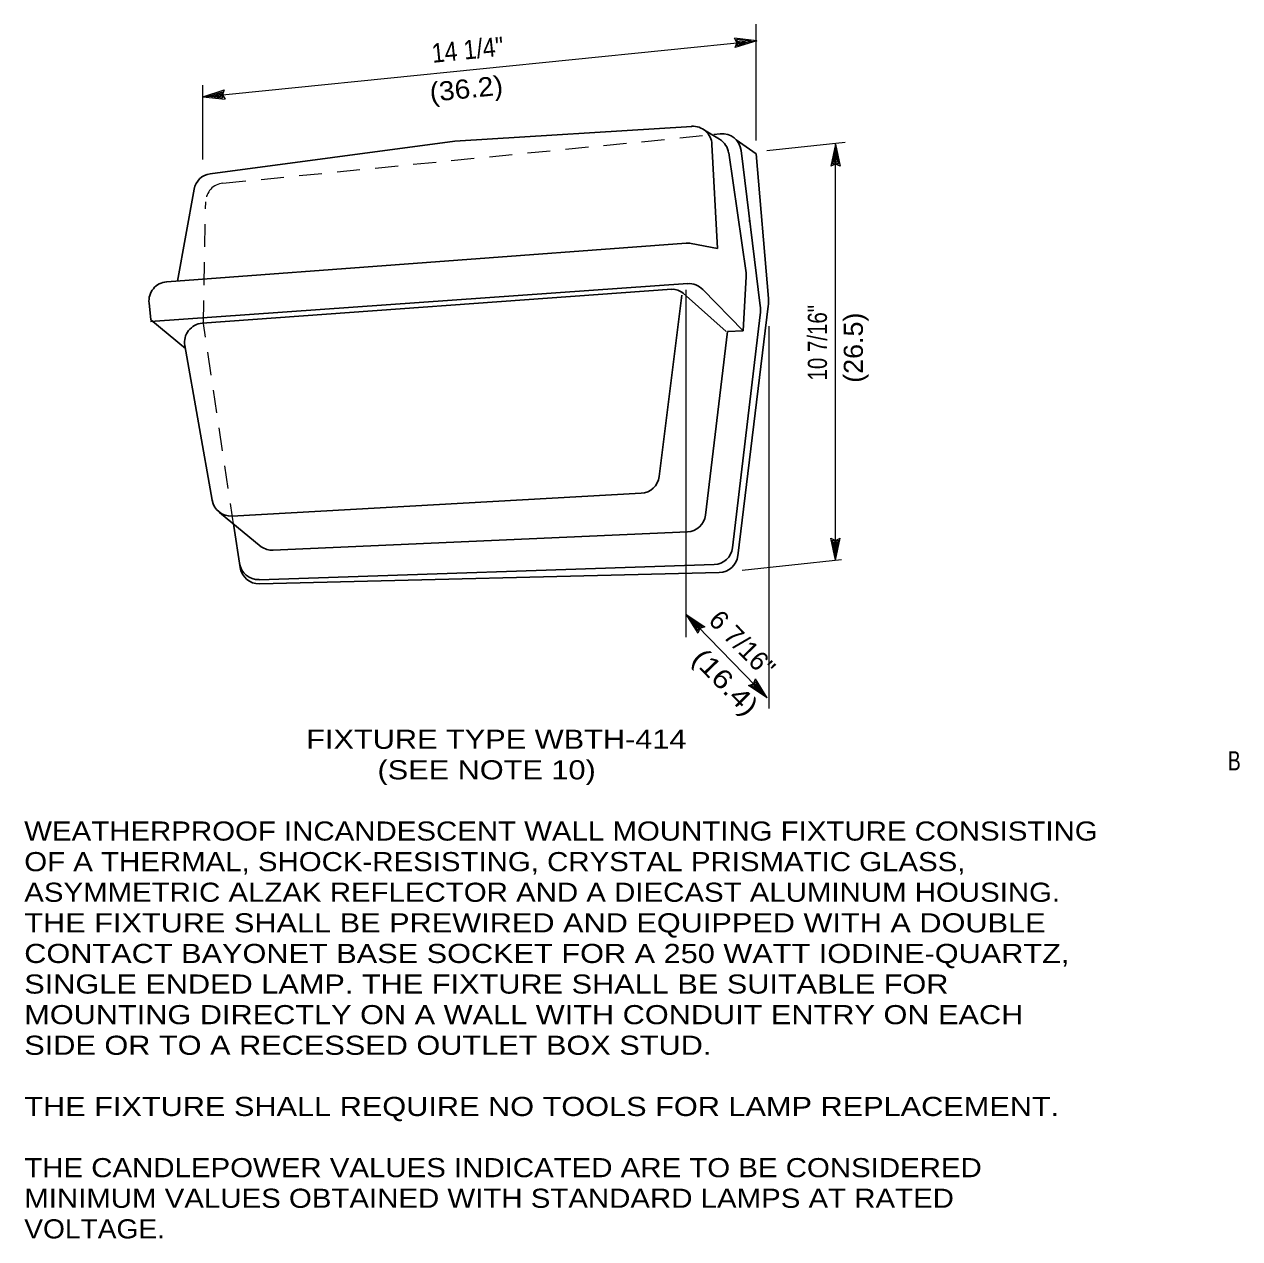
# Model space of a CAD drawing. Extents: x -39.6 to 16.1, y -17.6 to 34.
# Drawn here: x -1.77 to 6.18, y 25.94 to 33.88 of the extents above; entities that cross this region are included whole.
import ezdxf
from ezdxf.enums import TextEntityAlignment as Align

# ---------------------------------------------------------------- set-up
doc = ezdxf.new("R2010")
doc.units = 0
doc.header["$LTSCALE"] = 0.05
doc.linetypes.add('MEDIUM_DASHED', pattern=[4.5, 3, -1.5])
doc.layers.add('1', color=7, linetype='Continuous', lineweight=13)

msp = doc.modelspace()

# ---------------------------------------------------------------- linework, layer by layer
at = {"layer": '1'}
for p, q in [((3.01679, 33.11742), (3.01679, 33.87642)), ((-0.60021, 33.40242), (3.02079, 33.76942)), ((3.02079, 33.76942), (2.87479, 33.78542)), ((3.02079, 33.76942), (2.88079, 33.72442)), ((2.98379, 33.76542), (2.88879, 33.77642)), ((2.89979, 33.75742), (2.88879, 33.77642)), ((2.98379, 33.76542), (2.89279, 33.73642)), ((2.94779, 33.76242), (2.90279, 33.76642)), ((2.90779, 33.75842), (2.90279, 33.76642)), ((2.89279, 33.73642), (2.89979, 33.75742)), ((2.94779, 33.76242), (2.90479, 33.74742)), ((2.90479, 33.74742), (2.90779, 33.75842)), ((-0.60021, 32.99342), (-0.60021, 33.47942)), ((-0.60021, 33.40242), (-0.46021, 33.44742)), ((-0.60021, 33.40242), (-0.45421, 33.38642)), ((-0.56321, 33.40642), (-0.47221, 33.43542)), ((-0.56321, 33.40642), (-0.46821, 33.39542)), ((-0.52721, 33.40942), (-0.48421, 33.42442)), ((-0.52721, 33.40942), (-0.48221, 33.40542)), ((-0.48421, 33.42442), (-0.48721, 33.41342)), ((-0.48721, 33.41342), (-0.48221, 33.40542)), ((-0.47221, 33.43542), (-0.47921, 33.41442)), ((-0.47921, 33.41442), (-0.46821, 33.39542)), ((3.08779, 33.05142), (3.59979, 33.10542)), ((3.53579, 33.09242), (3.50479, 32.94842)), ((3.53579, 33.05542), (3.51579, 32.96142)), ((3.53579, 30.37342), (3.53579, 33.09242)), ((3.53579, 33.09242), (3.56679, 32.94842)), ((3.53579, 33.05542), (3.55579, 32.96142)), ((3.53579, 32.97042), (3.51579, 32.96142)), ((3.53579, 33.01942), (3.52679, 32.97442)), ((3.53579, 32.97842), (3.52679, 32.97442)), ((3.53579, 33.01942), (3.54579, 32.97442)), ((3.54579, 32.97442), (3.53579, 32.97842)), ((3.55579, 32.96142), (3.53579, 32.97042)), ((2.55879, 29.87142), (2.55879, 32.14042)), ((3.10179, 29.40442), (3.10179, 31.90442)), ((3.53579, 30.37342), (3.50479, 30.51742)), ((3.53579, 30.37342), (3.56679, 30.51742)), ((3.53579, 30.41042), (3.51579, 30.50442)), ((3.51579, 30.50442), (3.53579, 30.49542)), ((3.53579, 30.44642), (3.52579, 30.49142)), ((3.52579, 30.49142), (3.53579, 30.48742)), ((3.53579, 30.41042), (3.55579, 30.50442)), ((3.53579, 30.49542), (3.55579, 30.50442)), ((3.53579, 30.44642), (3.54479, 30.49142)), ((3.53579, 30.48742), (3.54479, 30.49142)), ((2.92579, 30.30942), (3.57579, 30.37842)), ((2.55779, 30.02142), (2.68079, 29.93942)), ((2.55779, 30.02142), (2.63579, 29.89642)), ((2.58379, 29.99442), (2.66379, 29.94142)), ((2.58379, 29.99442), (2.63479, 29.91342)), ((2.60879, 29.96942), (2.63379, 29.93042)), ((2.60879, 29.96942), (2.64679, 29.94342)), ((2.63679, 29.93942), (2.63379, 29.93042)), ((2.64279, 29.93342), (2.63479, 29.91342)), ((2.64679, 29.94342), (2.63679, 29.93942)), ((2.66379, 29.94142), (2.64279, 29.93342)), ((2.98379, 29.55342), (3.00479, 29.56142)), ((3.00079, 29.55142), (3.01079, 29.55542)), ((3.00479, 29.56142), (3.01279, 29.58142)), ((3.01079, 29.55542), (3.01379, 29.56442)), ((3.08979, 29.47342), (3.01179, 29.59842)), ((3.06379, 29.50042), (3.01279, 29.58142)), ((3.03879, 29.52542), (3.01379, 29.56442)), ((3.06379, 29.50042), (2.98379, 29.55342)), ((3.03879, 29.52542), (3.00079, 29.55142))]:
    msp.add_line(p, q, dxfattribs=at)
at = {"layer": '1', "linetype": 'MEDIUM_DASHED'}
msp.add_line((-0.46821, 32.83842), (2.72479, 33.15442), dxfattribs=at)
at = {"layer": '1', "lineweight": 25}
for p, q in [((2.67879, 33.18442), (2.77779, 33.12542)), ((2.74079, 33.15642), (2.78279, 33.16042)), ((2.76479, 32.41042), (2.72779, 33.09142)), ((3.01679, 33.03042), (2.88579, 33.12242)), ((3.04379, 32.03742), (2.91879, 33.05142)), ((2.95079, 32.25242), (2.83779, 33.03542)), ((3.09679, 32.08542), (3.01679, 33.03042)), ((-0.76621, 32.19842), (-0.65721, 32.79842)), ((-0.83621, 32.19342), (2.55879, 32.44642)), ((2.76479, 32.41042), (2.59179, 32.44442)), ((-0.94221, 31.93442), (2.56979, 32.18142)), ((2.93179, 31.87242), (2.95179, 32.22742)), ((-0.60321, 31.92242), (2.46579, 32.14442)), ((2.38279, 30.92042), (2.53179, 32.10642)), ((2.53979, 32.11942), (2.82079, 31.86842)), ((2.66879, 32.14342), (2.93179, 31.87242)), ((-0.93921, 31.94442), (-0.95121, 32.05542)), ((2.89679, 30.40342), (3.09579, 32.03442)), ((-0.71421, 31.75842), (-0.93921, 31.94442)), ((2.86279, 30.45542), (3.04379, 31.97742)), ((2.68579, 30.66942), (2.83079, 31.86942)), ((2.83079, 31.86942), (2.93179, 31.87242)), ((-0.53921, 30.76542), (-0.71721, 31.77642)), ((-0.40921, 30.66242), (2.26579, 30.81142)), ((-0.21821, 30.46242), (-0.49021, 30.68642)), ((-0.35621, 30.32642), (-0.39721, 30.59542)), ((-0.14121, 30.43942), (2.56779, 30.55942)), ((-0.23221, 30.24642), (2.74279, 30.34542)), ((-0.22921, 30.21942), (2.77579, 30.29342))]:
    msp.add_line(p, q, dxfattribs=at)
at = {"layer": '1'}
for points in [[(2.88079, 33.72442), (2.89179, 33.75642), (2.87479, 33.78542)], [(-0.46021, 33.44742), (-0.47121, 33.41542), (-0.45421, 33.38642)], [(3.56679, 32.94842), (3.53579, 32.96242), (3.50479, 32.94842)], [(3.50479, 30.51742), (3.53579, 30.50342), (3.56679, 30.51742)], [(2.55779, 30.02142), (3.08979, 29.47342), (2.96679, 29.55542)], [(2.68079, 29.93942), (2.64879, 29.92842), (2.63579, 29.89642)], [(2.96679, 29.55542), (2.99879, 29.56642), (3.01179, 29.59842)]]:
    msp.add_lwpolyline(points, dxfattribs=at)
at = {"layer": '1', "lineweight": 25}
msp.add_lwpolyline([(-0.55121, 32.89942), (1.04679, 33.11342), (2.59579, 33.20942)], dxfattribs=at)
at = {"layer": '1', "linetype": 'MEDIUM_DASHED'}
msp.add_lwpolyline([(-0.39721, 30.59542), (-0.59621, 31.92142), (-0.58121, 32.71642)], dxfattribs=at)
at = {"layer": '1', "lineweight": 25}
for centre, radius, start, end in [((2.60307, 33.085), 0.125, 3.14113, 93.56015), ((2.79501, 33.0361), 0.125, 7.01243, 95.65291), ((2.71359, 33.01776), 0.125, 8.24439, 59.03624), ((-0.53433, 32.77601), 0.125, 97.61177, 169.7121), ((2.72307, 32.6004), 0.25, 356.68658, 7.06204), ((2.56828, 32.3213), 0.125, 79.01135, 94.25494), ((-0.82717, 32.06868), 0.125, 94.26292, 186.30363), ((2.5788, 32.05647), 0.125, 44.15213, 94.01859), ((2.82738, 32.23446), 0.125, 356.71352, 8.26355), ((2.47299, 32.04456), 0.1, 48.27767, 94.13512), ((2.79578, 32.00716), 0.25, 353.21616, 7.02052), ((2.84792, 32.06457), 0.25, 353.04509, 4.85438), ((-0.59455, 31.79796), 0.125, 94.13065, 190.01105), ((2.25901, 30.93613), 0.125, 273.18584, 352.85024), ((-0.41605, 30.78716), 0.125, 190.01457, 273.18729), ((2.56182, 30.6842), 0.125, 272.53262, 353.11746), ((-0.14626, 30.56442), 0.125, 234.69561, 272.53412), ((2.73906, 30.46991), 0.125, 271.89718, 353.23382), ((-0.23619, 30.37175), 0.125, 188.77782, 271.88068), ((2.77308, 30.41883), 0.125, 271.41903, 353.05522), ((-0.2326, 30.34477), 0.125, 188.65755, 271.41167)]:
    msp.add_arc(centre, radius, start, end, dxfattribs=at)
at = {"layer": '1', "linetype": 'MEDIUM_DASHED'}
msp.add_arc((-0.45628, 32.71427), 0.125, 95.64689, 178.92266, dxfattribs=at)

# ---------------------------------------------------------------- texts
at = {"layer": '1'}
for s, rotation, width, p in [('14 1/4"', 5.773, 0.9, (1.13742, 33.64814)), ('(36.2)', 5.773, 1.1, (1.1282, 33.39336)), ('10 7/16"', 90, 0.8, (3.47979, 31.79542)), ('(26.5)', 90, 1.05, (3.71479, 31.76292)), ('(16.4)', 314.254, 1.2, (2.77165, 29.53488))]:
    msp.add_text(s, height=0.125, rotation=rotation, dxfattribs=dict(at, width=width)).set_placement(p, align=Align.CENTER)
msp.add_text('6 7/16"', height=0.125, rotation=314.254, dxfattribs=at).set_placement((2.88083, 29.78538), align=Align.CENTER)
at = {"layer": '1', "width": 1.2}
for s, p in [('FIXTURE TYPE WBTH-414', (1.31879, 29.14142)), ('(SEE NOTE 10)', (1.25529, 28.94142))]:
    msp.add_text(s, height=0.125, dxfattribs=at).set_placement(p, align=Align.CENTER)
at = {"layer": '1'}
for s, width, p in [('B', 0.75, (6.10079, 29.00042)), ('WEATHERPROOF INCANDESCENT WALL MOUNTING FIXTURE CONSISTING', 1.15, (-1.76721, 28.54142)), ('OF A THERMAL, SHOCK-RESISTING, CRYSTAL PRISMATIC GLASS,', 1.15, (-1.76721, 28.34142)), ('ASYMMETRIC ALZAK REFLECTOR AND A DIECAST ALUMINUM HOUSING.', 1.15, (-1.76721, 28.14142)), ('THE FIXTURE SHALL BE PREWIRED AND EQUIPPED WITH A DOUBLE', 1.2, (-1.76721, 27.94142)), ('CONTACT BAYONET BASE SOCKET FOR A 250 WATT IODINE-QUARTZ,', 1.2, (-1.76721, 27.74142)), ('SINGLE ENDED LAMP. THE FIXTURE SHALL BE SUITABLE FOR', 1.2, (-1.76721, 27.54142)), ('MOUNTING DIRECTLY ON A WALL WITH CONDUIT ENTRY ON EACH', 1.2, (-1.76721, 27.34142)), ('SIDE OR TO A RECESSED OUTLET BOX STUD.', 1.2, (-1.76721, 27.14142)), ('THE FIXTURE SHALL REQUIRE NO TOOLS FOR LAMP REPLACEMENT.', 1.2, (-1.76721, 26.74142)), ('THE CANDLEPOWER VALUES INDICATED ARE TO BE CONSIDERED', 1.15, (-1.76721, 26.34142)), ('MINIMUM VALUES OBTAINED WITH STANDARD LAMPS AT RATED', 1.15, (-1.76721, 26.14142)), ('VOLTAGE.', 1.1, (-1.76721, 25.94142))]:
    msp.add_text(s, height=0.125, dxfattribs=dict(at, width=width)).set_placement(p)

doc.saveas('drawing.dxf')
